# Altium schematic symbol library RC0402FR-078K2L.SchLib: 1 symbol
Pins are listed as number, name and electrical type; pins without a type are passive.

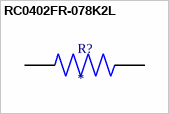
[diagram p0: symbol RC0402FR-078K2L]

## RC0402FR-078K2L
designator R?
8.2 kOhms Â±1% 0.063W, 1/16W Chip Resistor 0402 (1005 Metric) Moisture Resistant Thick Film; MF: Yageo; MP: RC0402FR-078K2L
footprint RESC1005X40N
pins: 1, 2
